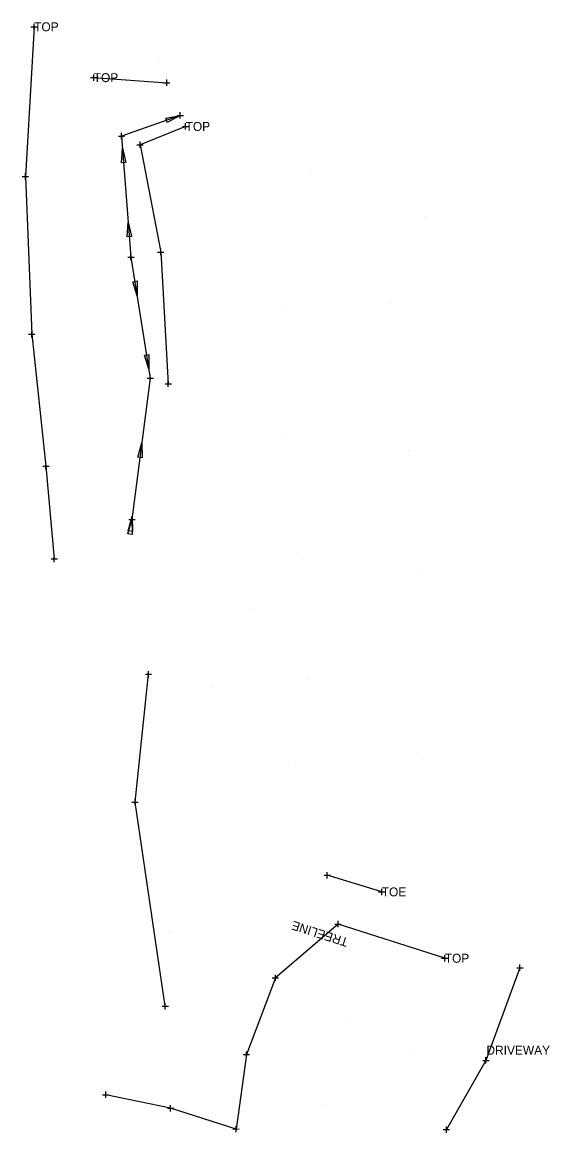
# Model space of a CAD drawing. Extents: x 1733239 to 1734352, y 466612 to 468622.
# Drawn here: x 1733850 to 1733956.6, y 467371.9 to 467596 of the extents above; entities that cross this region are included whole.
import ezdxf

# ---------------------------------------------------------------- set-up
doc = ezdxf.new("R2010")
doc.units = 0
for name, color, linetype in [('S_Terrain_Breaklines', 7, 'Continuous'), ('S_Terrain_Holes', 7, 'Continuous'), ('S_Terrain_Islands', 7, 'Continuous'), ('S_Terrain_Major_Contours', 7, 'Continuous'), ('S_Terrain_Minor_Contours', 7, 'Continuous'), ('S_Terrain_Voids', 7, 'Continuous'), ('S_Traffic_Sign_SinglePost', 7, 'Continuous')]:
    doc.layers.add(name, color=color, linetype=linetype)

msp = doc.modelspace()

# ---------------------------------------------------------------- linework, layer by layer
at = {"layer": 'S_Terrain_Breaklines'}
msp.add_lwpolyline([(1733935.36, 467407.1), (1733913.82, 467414), (1733901.17, 467403.15)], dxfattribs=at)
at = {"layer": 'S_Terrain_Holes'}
msp.add_line((1733864.48, 467584.82), (1733864.48, 467584.82), dxfattribs=at)
for points in [[(1733852.46, 467595.08), (1733850.68, 467564.88), (1733851.98, 467533.03), (1733854.82, 467506.44), (1733856.5, 467487.71)], [(1733864.48, 467584.82), (1733879.24, 467583.79)], [(1733883.04, 467574.97), (1733873.85, 467571.27), (1733878.02, 467549.62), (1733879.53, 467523.04)], [(1733878.93, 467397.41), (1733872.83, 467438.62), (1733875.54, 467464.42)], [(1733922.64, 467420.49), (1733911.64, 467423.86)], [(1733935.36, 467407.1), (1733913.82, 467414), (1733901.17, 467403.15), (1733895.33, 467387.68), (1733893.22, 467372.64), (1733880.01, 467376.84), (1733866.91, 467379.55)]]:
    msp.add_lwpolyline(points, dxfattribs=at)
at = {"layer": 'S_Terrain_Islands'}
msp.add_lwpolyline([(1733950.53, 467405.2), (1733943.67, 467386.5), (1733935.69, 467372.52)], dxfattribs=at)
at = {"layer": 'S_Terrain_Major_Contours'}
for p, q in [((1733877.79, 467587.92), (1733877.79, 467587.92)), ((1733908.41, 467565.26), (1733908.41, 467565.26)), ((1733931.26, 467556.78), (1733931.26, 467556.78)), ((1733902.87, 467537.94), (1733902.87, 467537.94)), ((1733924.45, 467539.45), (1733924.45, 467539.45)), ((1733902.81, 467513.08), (1733902.81, 467513.08)), ((1733928.02, 467509.48), (1733928.02, 467509.48)), ((1733906.7, 467487.48), (1733906.7, 467487.48)), ((1733930.3, 467484.64), (1733930.3, 467484.64)), ((1733896.04, 467477.46), (1733896.04, 467477.46)), ((1733888.17, 467461.75), (1733888.17, 467461.75)), ((1733907.83, 467463.34), (1733907.83, 467463.34)), ((1733904.08, 467446.04), (1733904.08, 467446.04)), ((1733930.95, 467447.18), (1733930.95, 467447.18)), ((1733879.79, 467412.44), (1733879.79, 467412.44)), ((1733915.79, 467394.56), (1733915.79, 467394.56)), ((1733928.42, 467388.39), (1733928.42, 467388.39)), ((1733910.75, 467377.52), (1733910.75, 467377.52))]:
    msp.add_line(p, q, dxfattribs=at)
at = {"layer": 'S_Terrain_Minor_Contours'}
for p, q in [((1733852.46, 467594.44), (1733852.46, 467595.71)), ((1733851.82, 467595.08), (1733853.1, 467595.08)), ((1733852.46, 467595.08), (1733852.46, 467595.08)), ((1733863.84, 467584.82), (1733865.11, 467584.82)), ((1733863.84, 467584.82), (1733865.11, 467584.82)), ((1733864.48, 467584.18), (1733864.48, 467585.45)), ((1733864.48, 467584.18), (1733864.48, 467585.45)), ((1733864.48, 467584.82), (1733864.48, 467584.82)), ((1733864.48, 467584.82), (1733864.48, 467584.82)), ((1733878.6, 467583.78), (1733879.88, 467583.79)), ((1733879.24, 467583.15), (1733879.24, 467584.42)), ((1733879.24, 467583.79), (1733879.24, 467583.79)), ((1733881.97, 467576.56), (1733881.96, 467577.83)), ((1733881.97, 467576.56), (1733881.96, 467577.83)), ((1733881.33, 467577.2), (1733882.6, 467577.2)), ((1733881.33, 467577.2), (1733882.6, 467577.2)), ((1733881.97, 467577.2), (1733881.97, 467577.2)), ((1733881.97, 467577.2), (1733881.97, 467577.2)), ((1733883.04, 467574.34), (1733883.04, 467575.61)), ((1733870.09, 467572.37), (1733870.09, 467573.65)), ((1733882.4, 467574.97), (1733883.67, 467574.98)), ((1733883.04, 467574.97), (1733883.04, 467574.97)), ((1733869.46, 467573.01), (1733870.73, 467573.01)), ((1733870.09, 467573.01), (1733870.09, 467573.01)), ((1733873.21, 467571.27), (1733874.49, 467571.27)), ((1733873.85, 467570.63), (1733873.85, 467571.9)), ((1733873.85, 467571.27), (1733873.85, 467571.27)), ((1733850.04, 467564.87), (1733851.32, 467564.88)), ((1733850.68, 467564.24), (1733850.68, 467565.51)), ((1733850.68, 467564.88), (1733850.68, 467564.88)), ((1733872.01, 467547.97), (1733872.01, 467549.24)), ((1733877.39, 467549.62), (1733878.66, 467549.62)), ((1733878.02, 467548.99), (1733878.02, 467550.26)), ((1733878.02, 467549.62), (1733878.02, 467549.62)), ((1733871.38, 467548.6), (1733872.65, 467548.6)), ((1733872.01, 467548.6), (1733872.01, 467548.6)), ((1733851.35, 467533.03), (1733852.62, 467533.03)), ((1733851.98, 467532.4), (1733851.98, 467533.67)), ((1733851.98, 467533.03), (1733851.98, 467533.03)), ((1733875.27, 467524.19), (1733876.54, 467524.19)), ((1733875.9, 467523.55), (1733875.9, 467524.83)), ((1733875.9, 467524.19), (1733875.9, 467524.19)), ((1733878.89, 467523.04), (1733880.17, 467523.04)), ((1733879.53, 467522.4), (1733879.53, 467523.68)), ((1733879.53, 467523.04), (1733879.53, 467523.04)), ((1733854.19, 467506.44), (1733855.46, 467506.44)), ((1733854.82, 467505.8), (1733854.82, 467507.07)), ((1733854.82, 467506.44), (1733854.82, 467506.44)), ((1733871.57, 467495.64), (1733872.84, 467495.65)), ((1733872.21, 467495.01), (1733872.21, 467496.28)), ((1733872.21, 467495.64), (1733872.21, 467495.64)), ((1733856.5, 467487.07), (1733856.5, 467488.34)), ((1733855.86, 467487.71), (1733857.14, 467487.71)), ((1733856.5, 467487.71), (1733856.5, 467487.71)), ((1733874.91, 467464.42), (1733876.18, 467464.42)), ((1733875.54, 467463.78), (1733875.54, 467465.06)), ((1733875.54, 467464.42), (1733875.54, 467464.42)), ((1733872.83, 467437.98), (1733872.83, 467439.26)), ((1733872.2, 467438.62), (1733873.47, 467438.62)), ((1733872.83, 467438.62), (1733872.83, 467438.62)), ((1733911, 467423.85), (1733912.28, 467423.86)), ((1733911.64, 467423.22), (1733911.64, 467424.49)), ((1733911.64, 467423.86), (1733911.64, 467423.86)), ((1733922.64, 467419.85), (1733922.64, 467421.12)), ((1733922, 467420.48), (1733923.28, 467420.49)), ((1733922.64, 467420.49), (1733922.64, 467420.49)), ((1733913.82, 467413.36), (1733913.81, 467414.63)), ((1733913.82, 467413.36), (1733913.81, 467414.63)), ((1733913.18, 467414), (1733914.45, 467414)), ((1733913.18, 467414), (1733914.45, 467414)), ((1733913.82, 467414), (1733913.82, 467414)), ((1733913.82, 467414), (1733913.82, 467414)), ((1733935.36, 467406.46), (1733935.36, 467407.73)), ((1733935.36, 467406.46), (1733935.36, 467407.73)), ((1733934.72, 467407.1), (1733936, 467407.1)), ((1733934.72, 467407.1), (1733936, 467407.1)), ((1733935.36, 467407.1), (1733935.36, 467407.1)), ((1733935.36, 467407.1), (1733935.36, 467407.1)), ((1733949.89, 467405.2), (1733951.17, 467405.2)), ((1733950.53, 467404.56), (1733950.53, 467405.84)), ((1733950.53, 467405.2), (1733950.53, 467405.2)), ((1733900.53, 467403.15), (1733901.8, 467403.15)), ((1733900.53, 467403.15), (1733901.8, 467403.15)), ((1733901.17, 467402.52), (1733901.16, 467403.79)), ((1733901.17, 467402.52), (1733901.16, 467403.79)), ((1733901.17, 467403.15), (1733901.17, 467403.15)), ((1733901.17, 467403.15), (1733901.17, 467403.15)), ((1733878.29, 467397.41), (1733879.56, 467397.42)), ((1733878.93, 467396.78), (1733878.92, 467398.05)), ((1733878.93, 467397.41), (1733878.93, 467397.41)), ((1733894.69, 467387.68), (1733895.96, 467387.68)), ((1733895.33, 467387.04), (1733895.33, 467388.31)), ((1733895.33, 467387.68), (1733895.33, 467387.68)), ((1733943.03, 467386.5), (1733944.3, 467386.5)), ((1733943.67, 467385.86), (1733943.66, 467387.13)), ((1733943.67, 467386.5), (1733943.67, 467386.5)), ((1733866.28, 467379.55), (1733867.55, 467379.55)), ((1733866.91, 467378.91), (1733866.91, 467380.18)), ((1733866.91, 467379.55), (1733866.91, 467379.55)), ((1733879.37, 467376.84), (1733880.64, 467376.84)), ((1733880.01, 467376.21), (1733880.01, 467377.48)), ((1733880.01, 467376.84), (1733880.01, 467376.84)), ((1733892.59, 467372.64), (1733893.86, 467372.65)), ((1733893.22, 467372.01), (1733893.22, 467373.28)), ((1733893.22, 467372.64), (1733893.22, 467372.64)), ((1733935.05, 467372.52), (1733936.32, 467372.52)), ((1733935.69, 467371.88), (1733935.68, 467373.15)), ((1733935.69, 467372.52), (1733935.69, 467372.52))]:
    msp.add_line(p, q, dxfattribs=at)
at = {"layer": 'S_Terrain_Voids'}
for p, q in [((1733881.97, 467577.2), (1733881.97, 467577.2)), ((1733881.97, 467577.2), (1733881.97, 467577.2)), ((1733870.28, 467570.61), (1733870.28, 467570.61)), ((1733871.46, 467555.65), (1733871.46, 467555.65)), ((1733873.26, 467540.78), (1733873.26, 467540.78)), ((1733875.62, 467525.96), (1733875.62, 467525.96)), ((1733874.21, 467511.1), (1733874.21, 467511.1)), ((1733872.21, 467495.64), (1733872.21, 467495.64)), ((1733872.28, 467496.23), (1733872.28, 467496.23))]:
    msp.add_line(p, q, dxfattribs=at)
msp.add_lwpolyline([(1733881.97, 467577.2), (1733870.09, 467573.01), (1733872.01, 467548.6), (1733875.9, 467524.19), (1733872.21, 467495.64)], dxfattribs=at)
for points in [[(1733881.97, 467577.2), (1733879.32, 467575.79), (1733879.02, 467576.63)], [(1733870.28, 467570.61), (1733870.96, 467567.69), (1733870.07, 467567.62)], [(1733871.46, 467555.65), (1733872.13, 467552.73), (1733871.25, 467552.66)], [(1733873.26, 467540.78), (1733872.35, 467543.64), (1733873.23, 467543.78)], [(1733875.62, 467525.96), (1733874.71, 467528.82), (1733875.59, 467528.96)], [(1733874.21, 467511.1), (1733874.27, 467508.1), (1733873.39, 467508.21)], [(1733872.21, 467495.64), (1733872.27, 467492.64), (1733871.39, 467492.76)], [(1733872.28, 467496.23), (1733872.34, 467493.23), (1733871.46, 467493.34)]]:
    msp.add_lwpolyline(points, close=True, dxfattribs=at)

# ---------------------------------------------------------------- texts
at = {"layer": 'S_Traffic_Sign_SinglePost'}
for s, p in [('TOP', (1733852.46, 467594.18)), ('TOP', (1733864.48, 467583.92)), ('TOP', (1733864.48, 467583.92)), ('TOP', (1733883.04, 467574.07)), ('TOE', (1733922.64, 467419.59)), ('TOP', (1733935.36, 467406.2)), ('TOP', (1733935.36, 467406.2)), ('DRIVEWAY', (1733943.78, 467387.65))]:
    msp.add_text(s, height=1.8, dxfattribs=at).set_placement(p)
msp.add_text('TREELINE', height=1.8, rotation=162.2408, dxfattribs=at).set_placement((1733916.02, 467411.09))

doc.saveas('drawing.dxf')
